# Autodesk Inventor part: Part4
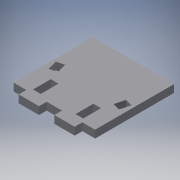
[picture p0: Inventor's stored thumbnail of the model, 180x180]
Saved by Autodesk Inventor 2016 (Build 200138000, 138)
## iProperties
Created: 2017-06
Part Number: Part4
Material: Generic
Document SubType Name: Modeling
Designer: laboratorioesan
Density: 1 g/cm^3
Appearance: Default
Author: laboratorioesan
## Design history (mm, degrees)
sketch "Sketch1"
  geometry: L1 (5, 0)-(5, 3) reference; L2 (-27, 0)-(-27, 3) reference; L3 (0, 0)-(-8, 0) reference; L4 (0, 0)-(0, 3) reference; L5 (-8, 3)-(0, 3) reference; L6 (-8, 0)-(-8, 3) reference; L7 (-14, 0)-(-22, 0) reference; L8 (-14, 0)-(-14, 3) reference; L9 (-22, 3)-(-14, 3) reference; L10 (-22, 0)-(-22, 3) reference; L11 (-27, 3)-(-27, 34); L12 (-27, 34)-(5, 34); L13 (5, 34)-(5, 3); L14 (-17.85, 3)-(-17.85, 13); L15 (-17.85, 13)-(-4.15, 13); L16 (-4.15, 13)-(-4.15, 3); L17 (-4.15, 4.5)-(-1.15, 4.5); L18 (-1.15, 4.5)-(-1.15, 11.5); L19 (-1.15, 11.5)-(-4.15, 11.5); L20 (-4.15, 11.5)-(-4.15, 4.5); L21 (-17.85, 11.5)-(-20.85, 11.5); L22 (-20.85, 11.5)-(-20.85, 4.5); L23 (-20.85, 4.5)-(-17.85, 4.5); L24 (-17.85, 4.5)-(-17.85, 11.5); L25 (-1.15, 11.5)-(5, 34); L26 (-0.095, 15.358)-(2.798, 14.567); L27 (2.798, 14.567)-(3.853, 18.426); L28 (3.853, 18.426)-(0.959, 19.217); L29 (-0.095, 15.358)-(0.959, 19.217); L30 (-20.85, 11.5)-(-27, 34); L31 (-21.905, 15.358)-(-24.798, 14.567); L32 (-24.798, 14.567)-(-25.853, 18.426); L33 (-25.853, 18.426)-(-22.959, 19.217); L34 (-22.959, 19.217)-(-21.905, 15.358); L35 (5, 3)-(0, 3); L36 (-27, 3)-(-22.2, 3); L37 (-22.2, 3)-(-22.2, 0); L38 (-22.2, 0)-(-13.8, 0); L39 (-13.8, 0)-(-13.8, 3); L40 (-13.8, 3)-(-8.2, 3); L41 (-8.2, 3)-(-8.2, 0); L42 (-8.2, 0)-(0.2, 0); L43 (0.2, 0)-(0.2, 3); 2 further points; 1 other entity
  constraints: 66 end point, 8 perpendicular, 7 parallel, 7 point on line, 4 vertical, 3 horizontal, 3 horizontal alignment, 2 collinear, 2 midpoint, 1 coincident, 1 vertical alignment, 9 other
  dimensions: "d0" = 31 distance of L11.start L11.end; "d5" = 13.7 distance of L14.end L15.end; "d6" = 10 distance of L14.start L14.end; "d7" = 3 distance of L19.end L18.end; "d8" = 7 distance of L18.end L17.end; "d9" = 1.5 distance from line of L5 L17.end; "d10" = 3 distance of L23.end L22.end; "d11" = 3 distance of L26.start L26.end; "d12" = 4 distance of L26.end L27.end; "d16" = 4 distance of L18.end L26.start; "d20" = 1.5 distance of L14.end L21.start; "d23" = 3 distance of L31.start L31.end; "d24" = 4 distance of L31.end L32.end; "d25" = 0.2 distance of L3.start L42.end; "d26" = 0.2 distance of L3.end L41.end; "d27" = 0.2 distance of L7.start L38.end; "d28" = 0.2 distance from line of L10 L37.end
extrude "Extrusion1" new body sketch "Sketch1" distance "d29" = 3; taper "d30" = 0 deg
body "Solid1"
node "Reference1"
node "Reference2"
node "Reference3"
